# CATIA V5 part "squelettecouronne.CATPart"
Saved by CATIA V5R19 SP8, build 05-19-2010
Part number: squelettecouronne
Bounding box of the stored display mesh (mm): x -103.938 to 128.782, y -124.939 to 124.939, z -124.939 to 124.939
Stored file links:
  U:\Rendu_cfao_elguidj\squelettecouronne.CATPart
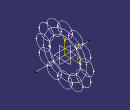
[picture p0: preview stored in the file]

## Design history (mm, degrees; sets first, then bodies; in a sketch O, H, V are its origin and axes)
Parameters
  `Rnominal pignon` = 24.2485 mm
  `Rtête pignon` = 31.25 mm
Body1 (main body)
  Plane1: stored without definition
  Sketch1 on Plane1, origin (0, 0, 0), H (-1, 0, 0), V (0, 0, 1)
    line L1 (103.9376, 0) -> (-128.7821, 0)
    point P1 (103.9376, 0)
    coincidence: P1 H
    horizontal: L1 H
  Sketch2 on yz-plane, origin (0, 0, 0), H (0, 1, 0), V (0, 0, 1)
    circle A1 centre (0, 0) radius 93.689
    construction circle A2 centre (-46.8445, 81.1371) radius 24.2485
    point P1 (-46.8445, 81.1371)
    construction circle A3 centre (0, 93.689) radius 24.2485
    point P2 (0, 93.689)
    construction circle A4 centre (93.689, 0) radius 24.2485
    construction circle A5 centre (-81.1371, 46.8445) radius 24.2485
    point P4 (-81.1371, 46.8445)
    construction circle A6 centre (-93.689, 0) radius 24.2485
    point P5 (-93.689, 0)
    point P6 (-81.1371, -46.8445)
    construction circle A7 centre (-81.1371, -46.8445) radius 24.2485
    construction circle A8 centre (-46.8445, -81.1371) radius 24.2485
    point P7 (-46.8445, -81.1371)
    construction circle A9 centre (0, -93.689) radius 24.2485
    point P8 (0, -93.689)
    point P9 (0, 55.5732)
    point P10 (0, 55.5732)
    point P11 (-39.2962, 39.2962)
    point P12 (69.4405, 0)
    point P13 (0, -55.5732)
    point P14 (0, -55.5732)
    point P15 (-39.2962, -39.2962)
    circle A10 centre (0, 93.689) radius 31.25
    circle A11 centre (-81.1371, 46.8445) radius 31.25
    point P17 (-81.1371, -46.8445)
    circle A12 centre (-81.1371, -46.8445) radius 31.25
    circle A13 centre (0, -93.689) radius 31.25
    circle A14 centre (93.689, 0) radius 31.25
    circle A15 centre (-93.689, 0) radius 31.25
    circle A16 centre (-46.8445, -81.1371) radius 31.25
    circle A17 centre (-46.8445, 81.1371) radius 31.25
    construction circle A18 centre (46.8445, 81.1371) radius 24.2485
    point P21 (46.8445, 81.1371)
    construction circle A19 centre (46.8445, -81.1371) radius 24.2485
    point P22 (46.8445, -81.1371)
    construction circle A20 centre (81.1371, 46.8445) radius 24.2485
    point P23 (81.1371, 46.8445)
    construction circle A21 centre (81.1371, -46.8445) radius 24.2485
    point P24 (81.1371, -46.8445)
    circle A22 centre (46.8445, 81.1371) radius 31.25
    circle A23 centre (81.1371, 46.8445) radius 31.25
    circle A24 centre (81.1371, -46.8445) radius 31.25
    circle A25 centre (46.8445, -81.1371) radius 31.25
    circle A26 centre (0, 0) radius 69.4405
    radius A4 = 24.2485 {= `Rnominal pignon`}
    radius A9 = 24.2485 {= `Rnominal pignon`}
    radius A8 = 24.2485 {= `Rnominal pignon`}
    radius A7 = 24.2485 {= `Rnominal pignon`}
    radius A6 = 24.2485 {= `Rnominal pignon`}
    radius A5 = 24.2485 {= `Rnominal pignon`}
    radius A2 = 24.2485 {= `Rnominal pignon`}
    radius A10 = 31.25 {= `Rtête pignon`}
    radius A14 = 31.25 {= `Rtête pignon`}
    radius A16 = 31.25 {= `Rtête pignon`}
    radius A3 = 24.2485 {= `Rnominal pignon`}
    radius A11 = 31.25 {= `Rtête pignon`}
    radius A18 = 24.2485 {= `Rnominal pignon`}
    radius A19 = 24.2485 {= `Rnominal pignon`}
    radius A20 = 24.2485 {= `Rnominal pignon`}
    radius A22 = 31.25 {= `Rtête pignon`}
    radius A23 = 31.25 {= `Rtête pignon`}
    radius A24 = 31.25 {= `Rtête pignon`}
    radius A25 = 31.25 {= `Rtête pignon`}
    coincidence: P1 A1, P2 A1, P4 A1, P5 A1, P6 A1, P7 A1, P8 A1, P17 A1, P21 A1, P22 A1, P23 A1, P24 A1, A26 P12
    tangency: A3 A2, A5 A2, A5 A6, A7 A6, A8 A7, A9 A8, A18 A3, A19 A9, A20 A18, A20 A4, A21 A19, A21 A4, A26 A20
    symmetry: P9 P13 H, P10 P14 H, P11 P15 H, A11 A12 H, A10 A13 H, A14 A15 V, A16 A17 H
    concentricity: A13 A9, A12 A7, A15 A6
